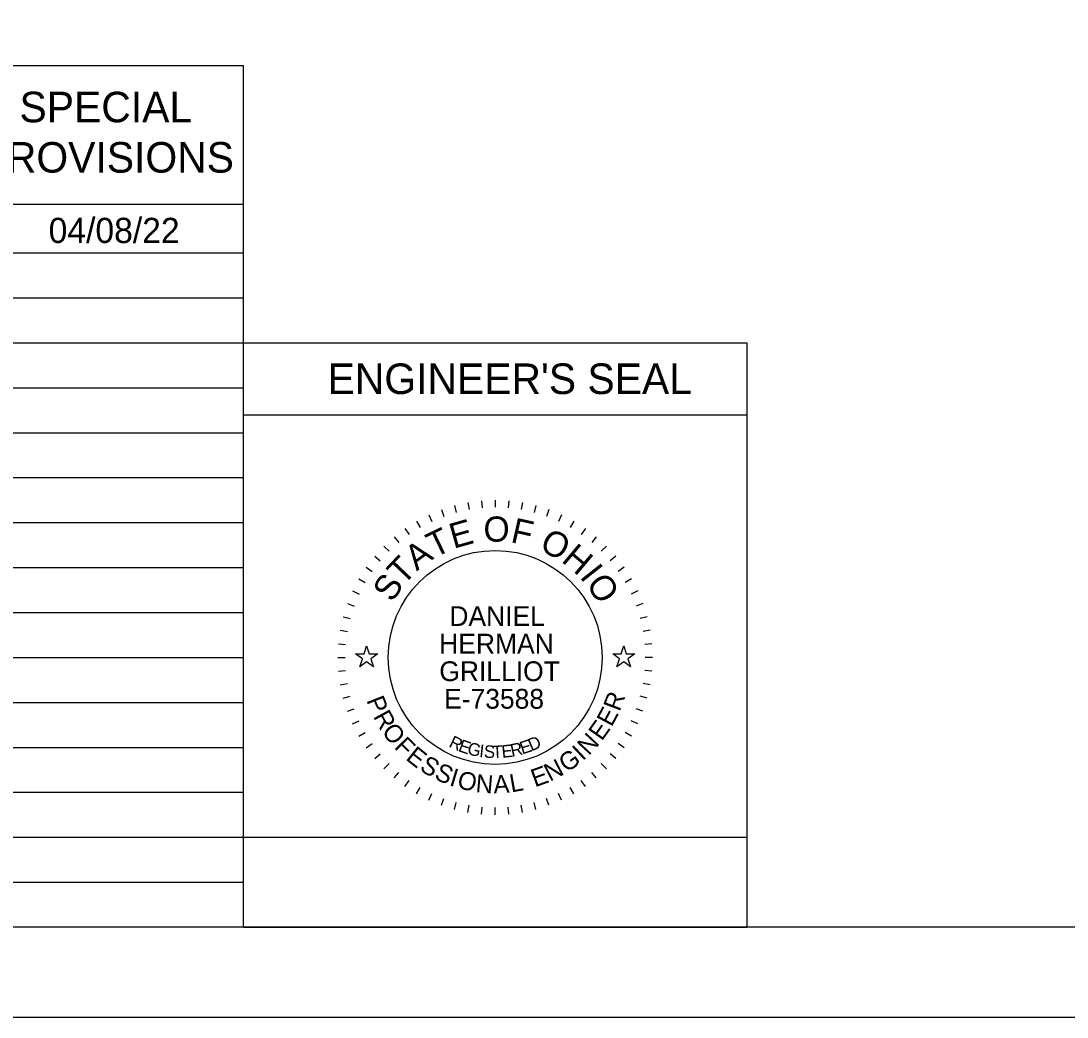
# Model space of a CAD drawing. Extents: x -31.7 to 34, y 0 to 22.
# Drawn here: x 22.36 to 28.18, y 0 to 5.54 of the extents above; entities that cross this region are included whole.
import ezdxf

# ---------------------------------------------------------------- set-up
doc = ezdxf.new("R2010")
doc.units = 0
for name, color, linetype in [('Default', 7, 'Continuous'), ('SH_Border', 7, 'Continuous'), ('SH_Cut_Line', 7, 'Continuous'), ('SH_Data', 7, 'Continuous'), ('SH_Text', 7, 'Continuous')]:
    doc.layers.add(name, color=color, linetype=linetype)

msp = doc.modelspace()

# ---------------------------------------------------------------- linework, layer by layer
at = {"layer": 'Default'}
for points in [[(24.2236, 2.02), (24.2705, 2.02), (24.285, 2.0645), (24.2995, 2.02), (24.3464, 2.02), (24.3085, 1.9924), (24.323, 1.9478), (24.285, 1.9754), (24.247, 1.9478), (24.2615, 1.9924)], [(25.6536, 2.02), (25.7005, 2.02), (25.715, 2.0645), (25.7295, 2.02), (25.7764, 2.02), (25.7385, 1.9924), (25.753, 1.9478), (25.715, 1.9754), (25.677, 1.9478), (25.6915, 1.9924)]]:
    msp.add_lwpolyline(points, close=True, dxfattribs=at)
at = {"layer": 'SH_Border'}
msp.add_lwpolyline([(1.5, 21.5), (33.5, 21.5), (33.5, 0.5), (1.5, 0.5)], close=True, dxfattribs=at)
at = {"layer": 'SH_Cut_Line'}
msp.add_lwpolyline([(0, 0), (34, 0), (34, 22), (0, 22)], close=True, dxfattribs=at)
at = {"layer": 'SH_Data'}
for p, q in [((10.15, 5.2917), (23.6, 5.2917)), ((23.6, 0.5), (23.6, 5.2917)), ((10.15, 4.5209), (23.6, 4.5209)), ((10.15, 4.25), (23.6, 4.25)), ((10.15, 4), (23.6, 4)), ((10.15, 3.75), (23.6, 3.75)), ((23.6, 0.5), (23.6, 3.75)), ((23.6, 3.75), (26.4, 3.75)), ((26.4, 3.75), (26.4, 0.5)), ((10.15, 3.5), (23.6, 3.5)), ((23.6, 3.35), (26.4, 3.35)), ((10.15, 3.25), (23.6, 3.25)), ((10.15, 3), (23.6, 3)), ((24.8481, 2.8617), (24.855, 2.8223)), ((24.9237, 2.8717), (24.9272, 2.8318)), ((25, 2.875), (25, 2.835)), ((25.0763, 2.8717), (25.0728, 2.8318)), ((25.1519, 2.8617), (25.145, 2.8223)), ((24.7007, 2.8222), (24.7144, 2.7846)), ((24.7735, 2.8452), (24.7839, 2.8065)), ((25.2265, 2.8452), (25.2161, 2.8065)), ((25.2993, 2.8222), (25.2856, 2.7846)), ((10.15, 2.75), (23.6, 2.75)), ((24.5625, 2.7578), (24.5825, 2.7231)), ((24.6302, 2.793), (24.6471, 2.7568)), ((25.3698, 2.793), (25.3529, 2.7568)), ((25.4375, 2.7578), (25.4175, 2.7231)), ((24.4981, 2.7168), (24.5211, 2.684)), ((25.5019, 2.7168), (25.4789, 2.684)), ((24.3813, 2.6187), (24.4096, 2.5904)), ((24.4376, 2.6703), (24.4633, 2.6396)), ((25.5624, 2.6703), (25.5367, 2.6396)), ((25.6187, 2.6187), (25.5904, 2.5904)), ((24.3297, 2.5624), (24.3604, 2.5367)), ((25.6703, 2.5624), (25.6396, 2.5367)), ((10.15, 2.5), (23.6, 2.5)), ((24.2832, 2.5019), (24.316, 2.4789)), ((25.7168, 2.5019), (25.684, 2.4789)), ((24.2422, 2.4375), (24.2769, 2.4175)), ((25.7578, 2.4375), (25.7231, 2.4175)), ((24.207, 2.3698), (24.2432, 2.3529)), ((25.793, 2.3698), (25.7568, 2.3529)), ((24.1778, 2.2993), (24.2154, 2.2856)), ((25.8222, 2.2993), (25.7846, 2.2856)), ((10.15, 2.25), (23.6, 2.25)), ((24.1548, 2.2265), (24.1935, 2.2161)), ((25.8452, 2.2265), (25.8065, 2.2161)), ((24.1383, 2.1519), (24.1777, 2.145)), ((25.8617, 2.1519), (25.8223, 2.145)), ((24.1283, 2.0763), (24.1682, 2.0728)), ((25.8717, 2.0763), (25.8318, 2.0728)), ((10.15, 2), (23.6, 2)), ((24.125, 2), (24.165, 2)), ((25.875, 2), (25.835, 2)), ((24.1283, 1.9237), (24.1682, 1.9272)), ((25.8717, 1.9237), (25.8318, 1.9272)), ((24.1383, 1.8481), (24.1777, 1.855)), ((25.8617, 1.8481), (25.8223, 1.855)), ((10.15, 1.75), (23.6, 1.75)), ((24.1548, 1.7735), (24.1935, 1.7839)), ((25.8452, 1.7735), (25.8065, 1.7839)), ((24.1778, 1.7007), (24.2154, 1.7144)), ((25.8222, 1.7007), (25.7846, 1.7144)), ((24.207, 1.6302), (24.2432, 1.6471)), ((25.793, 1.6302), (25.7568, 1.6471)), ((24.2422, 1.5625), (24.2769, 1.5825)), ((25.7578, 1.5625), (25.7231, 1.5825)), ((24.2832, 1.4981), (24.316, 1.5211)), ((25.7168, 1.4981), (25.684, 1.5211)), ((10.15, 1.5), (23.6, 1.5)), ((24.3297, 1.4376), (24.3604, 1.4633)), ((25.6703, 1.4376), (25.6396, 1.4633)), ((24.3813, 1.3813), (24.4096, 1.4096)), ((25.6187, 1.3813), (25.5904, 1.4096)), ((24.4376, 1.3297), (24.4633, 1.3604)), ((25.5624, 1.3297), (25.5367, 1.3604)), ((24.4981, 1.2832), (24.5211, 1.316)), ((25.5019, 1.2832), (25.4789, 1.316)), ((10.15, 1.25), (23.6, 1.25)), ((24.5625, 1.2422), (24.5825, 1.2769)), ((24.6302, 1.207), (24.6471, 1.2432)), ((25.3698, 1.207), (25.3529, 1.2432)), ((25.4375, 1.2422), (25.4175, 1.2769)), ((24.7007, 1.1778), (24.7144, 1.2154)), ((24.7735, 1.1548), (24.7839, 1.1935)), ((24.8481, 1.1383), (24.855, 1.1777)), ((24.9237, 1.1283), (24.9272, 1.1682)), ((25, 1.125), (25, 1.165)), ((25.0763, 1.1283), (25.0728, 1.1682)), ((25.1519, 1.1383), (25.145, 1.1777)), ((25.2265, 1.1548), (25.2161, 1.1935)), ((25.2993, 1.1778), (25.2856, 1.2154)), ((10.15, 1), (23.6, 1)), ((10.15, 0.75), (23.6, 0.75)), ((23.6, 0.5), (26.4, 0.5))]:
    msp.add_line(p, q, dxfattribs=at)
msp.add_lwpolyline([(23.6, 0.5), (23.6, 1), (26.4, 1), (26.4, 0.5)], close=True, dxfattribs=at)
msp.add_circle((25, 2), 0.595, dxfattribs=at)

# ---------------------------------------------------------------- texts
for s, height, p in [("ENGINEER'S SEAL", 0.17, (24.0676, 3.465)), ('DANIEL', 0.11, (24.7451, 2.1749)), ('HERMAN', 0.11, (24.6885, 2.0216)), ('GRILLIOT', 0.11, (24.6892, 1.8684)), ('E-73588', 0.11, (24.7157, 1.7151))]:
    msp.add_text(s, height=height, dxfattribs=at).set_placement(p)
for s, height, rotation, p in [('E', 0.14, 15.75706, (24.7684, 2.6038)), ('O', 0.14, 359.78119, (24.9347, 2.6443)), ('F', 0.14, 347.43619, (25.0811, 2.6417)), ('T', 0.14, 25.71674, (24.6616, 2.5518)), ('O', 0.14, 332.25863, (25.2398, 2.6015)), ('A', 0.14, 36.47472, (24.5634, 2.4781)), ('H', 0.14, 319.91363, (25.3632, 2.5361)), ('T', 0.14, 46.4344, (24.4883, 2.3964)), ('I', 0.14, 308.36695, (25.4665, 2.4483)), ('S', 0.14, 57.19238, (24.4281, 2.3014)), ('O', 0.14, 303.14906, (25.5021, 2.4089)), ('R', 0.1, 69.23216, (25.6919, 1.6954)), ('P', 0.1, 291.49398, (24.2823, 1.7621)), ('R', 0.1, 298.73106, (24.319, 1.6717)), ('E', 0.1, 61.99508, (25.6476, 1.6098)), ('E', 0.1, 54.75801, (25.5933, 1.5314)), ('O', 0.1, 306.46664, (24.3655, 1.5883)), ('N', 0.1, 47.02243, (25.5202, 1.4508)), ('F', 0.1, 314.7068, (24.4343, 1.4983)), ('R', 0.07, 334.48695, (24.7375, 1.5051)), ('E', 0.07, 341.03996, (24.7906, 1.4801)), ('G', 0.07, 347.47515, (24.8414, 1.4618)), ('I', 0.07, 353.78581, (24.9091, 1.4468)), ('E', 0.07, 6.01169, (25.0389, 1.4412)), ('R', 0.07, 11.91844, (25.0925, 1.4474)), ('E', 0.07, 17.68363, (25.1498, 1.4602)), ('D', 0.07, 23.30524, (25.201, 1.477)), ('E', 0.1, 321.43929, (24.4978, 1.4348)), ('S', 0.07, 356.89262, (24.9358, 1.4429)), ('T', 0.07, 3.00609, (24.9857, 1.4387)), ('G', 0.1, 35.04687, (25.3981, 1.357)), ('I', 0.1, 43.28703, (25.4868, 1.4214)), ('S', 0.1, 328.67637, (24.5743, 1.3752)), ('S', 0.1, 335.91345, (24.6564, 1.3266)), ('E', 0.1, 20.07421, (25.2212, 1.277)), ('N', 0.1, 27.31129, (25.3045, 1.3075)), ('I', 0.1, 343.15053, (24.7406, 1.2897)), ('O', 0.1, 346.88592, (24.7839, 1.2751)), ('N', 0.1, 355.12608, (24.8888, 1.2517)), ('A', 0.1, 2.86166, (24.9923, 1.2437)), ('L', 0.1, 10.09874, (25.0894, 1.249))]:
    msp.add_text(s, height=height, rotation=rotation, dxfattribs=at).set_placement(p)
at = {"layer": 'SH_Text'}
for s, height, p in [('SPECIAL', 0.17, (22.3542, 4.9763)), ('PROVISIONS', 0.17, (22.1323, 4.6963)), ('04/08/22', 0.14, (22.5162, 4.305))]:
    msp.add_text(s, height=height, dxfattribs=at).set_placement(p)

doc.saveas('drawing.dxf')
